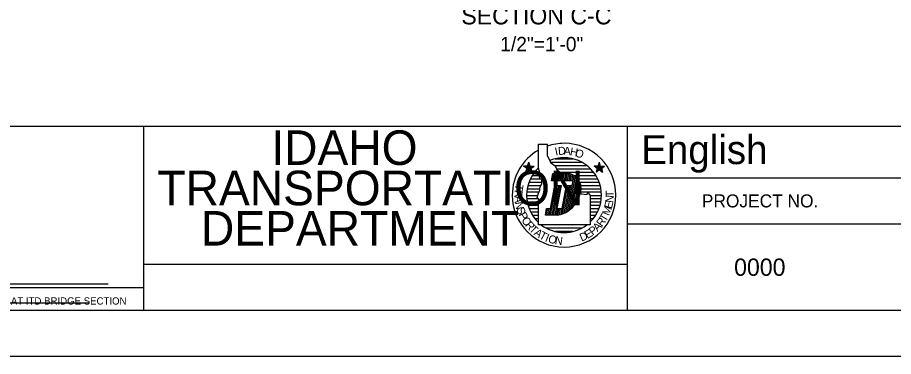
# Model space of a CAD drawing. Extents: x 0 to 68.6, y 0 to 47.1.
# Drawn here: x 25.26 to 44.28, y 0 to 7.35 of the extents above; entities that cross this region are included whole.
import ezdxf

# ---------------------------------------------------------------- set-up
doc = ezdxf.new("R2010")
doc.units = 0
for name, color, linetype in [('BORDER_ANNO_Cutsheet', 7, 'Continuous'), ('BRDG_ANNO_Anno-Large-Print', 7, 'Continuous'), ('BRDG_ANNO_Anno-Sheet', 7, 'Continuous'), ('BRDG_ANNO_Anno-Small-Print', 7, 'Continuous'), ('BRDG_ANNO_General-Notes', 7, 'Continuous')]:
    doc.layers.add(name, color=color, linetype=linetype)

msp = doc.modelspace()

# ---------------------------------------------------------------- linework, layer by layer
at = {"layer": 'BORDER_ANNO_Cutsheet'}
msp.add_lwpolyline([(0, 44), (68, 44), (68, 0), (0, 0)], close=True, dxfattribs=at)
at = {"layer": 'BRDG_ANNO_Anno-Large-Print'}
msp.add_line((23.799, 1.161), (26.811, 1.161), dxfattribs=at)
at = {"layer": 'BRDG_ANNO_Anno-Sheet'}
for p, q in [((3, 5), (38.5, 5)), ((28, 1), (28, 5)), ((38.5, 1), (38.5, 5)), ((38.5, 5), (67, 5)), ((36.569, 4.085), (36.569, 4.606)), ((36.569, 4.606), (36.766, 4.606)), ((36.766, 4.346), (36.766, 4.606)), ((36.331, 4.131), (36.359, 4.214)), ((36.359, 4.047), (36.359, 4.214)), ((36.386, 4.131), (36.359, 4.214)), ((36.766, 4.346), (36.819, 4.252)), ((36.819, 4.252), (36.829, 4.21)), ((36.829, 4.21), (36.932, 4.138)), ((36.834, 4.216), (37.501, 4.216)), ((36.93, 4.289), (37.316, 4.289)), ((37.864, 4.131), (37.891, 4.214)), ((37.891, 4.047), (37.891, 4.214)), ((37.919, 4.131), (37.891, 4.214)), ((36.402, 4.08), (36.245, 4.131)), ((36.331, 4.131), (36.245, 4.131)), ((36.315, 4.08), (36.245, 4.131)), ((36.386, 4.131), (36.288, 3.996)), ((36.315, 4.08), (36.288, 3.996)), ((36.359, 4.047), (36.288, 3.996)), ((36.315, 4.08), (36.474, 4.131)), ((36.331, 4.131), (36.43, 3.996)), ((36.359, 4.047), (36.43, 3.996)), ((36.386, 4.131), (36.474, 4.131)), ((36.402, 4.08), (36.474, 4.131)), ((36.402, 4.08), (36.43, 3.996)), ((36.484, 4.001), (36.587, 4.001)), ((36.549, 4.072), (36.572, 4.072)), ((36.589, 4.013), (36.569, 4.085)), ((36.589, 3.95), (36.589, 4.013)), ((36.93, 4.145), (37.614, 4.145)), ((36.932, 4.138), (36.965, 4.054)), ((36.957, 4.072), (37.701, 4.072)), ((36.965, 4.054), (37.069, 3.971)), ((37.031, 4.001), (37.765, 4.001)), ((37.935, 4.08), (37.776, 4.131)), ((37.847, 4.08), (37.776, 4.131)), ((37.864, 4.131), (37.776, 4.131)), ((37.919, 4.131), (37.82, 3.996)), ((37.847, 4.08), (37.82, 3.996)), ((37.891, 4.047), (37.82, 3.996)), ((37.847, 4.08), (38.005, 4.131)), ((37.864, 4.131), (37.962, 3.996)), ((37.891, 4.047), (37.962, 3.996)), ((37.919, 4.131), (38.005, 4.131)), ((37.935, 4.08), (38.005, 4.131)), ((37.935, 4.08), (37.962, 3.996)), ((36.394, 3.856), (36.596, 3.856)), ((36.434, 3.929), (36.585, 3.929)), ((36.589, 3.897), (36.589, 3.95)), ((36.6, 3.856), (36.589, 3.897)), ((36.641, 3.835), (36.6, 3.856)), ((36.641, 3.782), (36.641, 3.835)), ((36.85, 3.814), (36.881, 3.971)), ((37.322, 3.814), (36.85, 3.814)), ((36.879, 3.814), (36.907, 3.971)), ((36.881, 3.971), (37.225, 3.971)), ((36.91, 3.814), (36.94, 3.971)), ((36.942, 3.814), (36.971, 3.971)), ((36.974, 3.814), (37.004, 3.971)), ((37.005, 3.814), (37.035, 3.971)), ((37.038, 3.814), (37.066, 3.971)), ((37.069, 3.814), (37.099, 3.971)), ((37.101, 3.814), (37.13, 3.971)), ((37.133, 3.814), (37.163, 3.971)), ((37.165, 3.814), (37.194, 3.971)), ((37.196, 3.814), (37.226, 3.971)), ((37.199, 3.149), (37.344, 3.924)), ((37.227, 3.814), (37.256, 3.962)), ((37.235, 3.171), (37.373, 3.904)), ((37.26, 3.814), (37.286, 3.954)), ((37.273, 3.201), (37.399, 3.877)), ((37.291, 3.814), (37.315, 3.94)), ((37.304, 3.71), (37.322, 3.814)), ((37.311, 3.237), (37.425, 3.849)), ((37.337, 3.929), (37.815, 3.929)), ((37.351, 3.28), (37.45, 3.812)), ((37.42, 3.856), (37.855, 3.856)), ((38.5, 3.875), (44.5, 3.875)), ((36.325, 3.641), (36.596, 3.641)), ((36.341, 3.712), (36.623, 3.712)), ((36.362, 3.785), (36.637, 3.785)), ((36.6, 3.657), (36.62, 3.7)), ((36.6, 3.606), (36.6, 3.657)), ((36.62, 3.7), (36.641, 3.751)), ((36.641, 3.751), (36.641, 3.782)), ((36.829, 3.21), (36.922, 3.71)), ((36.832, 3.064), (36.954, 3.71)), ((36.865, 3.064), (36.986, 3.71)), ((36.896, 3.064), (37.017, 3.71)), ((36.922, 3.71), (37.06, 3.71)), ((36.929, 3.064), (37.05, 3.71)), ((37.06, 3.71), (36.966, 3.21)), ((37.087, 3.21), (37.181, 3.71)), ((37.094, 3.095), (37.209, 3.71)), ((37.127, 3.11), (37.24, 3.71)), ((37.163, 3.126), (37.273, 3.71)), ((37.181, 3.71), (37.304, 3.71)), ((37.394, 3.337), (37.474, 3.764)), ((37.444, 3.435), (37.491, 3.69)), ((37.465, 3.785), (37.886, 3.785)), ((37.489, 3.712), (37.909, 3.712)), ((37.495, 3.641), (37.925, 3.641)), ((36.312, 3.496), (36.555, 3.496)), ((36.315, 3.569), (36.581, 3.569)), ((36.316, 3.425), (36.562, 3.425)), ((36.538, 3.45), (36.557, 3.501)), ((36.569, 3.419), (36.538, 3.45)), ((36.557, 3.501), (36.569, 3.544)), ((36.569, 3.544), (36.6, 3.606)), ((37.481, 3.555), (37.496, 3.532)), ((37.485, 3.569), (37.935, 3.569)), ((37.496, 3.532), (37.559, 3.522)), ((37.559, 3.522), (37.621, 3.512)), ((37.621, 3.512), (37.652, 3.554)), ((37.652, 3.554), (37.694, 3.491)), ((37.69, 3.496), (37.938, 3.496)), ((37.694, 3.491), (37.694, 2.855)), ((37.695, 3.425), (37.934, 3.425)), ((36.326, 3.353), (36.596, 3.353)), ((36.343, 3.281), (36.567, 3.281)), ((36.589, 3.387), (36.569, 3.419)), ((36.569, 3.304), (36.6, 3.335)), ((36.569, 2.855), (36.569, 3.304)), ((36.6, 3.366), (36.589, 3.387)), ((36.6, 3.335), (36.6, 3.366)), ((37.694, 3.353), (37.924, 3.353)), ((37.694, 3.281), (37.907, 3.281)), ((36.367, 3.209), (36.565, 3.209)), ((36.399, 3.136), (36.565, 3.136)), ((36.44, 3.065), (36.566, 3.065)), ((36.719, 3.064), (36.746, 3.21)), ((36.985, 3.064), (36.719, 3.064)), ((36.737, 3.064), (36.765, 3.21)), ((36.746, 3.21), (36.829, 3.21)), ((36.77, 3.064), (36.797, 3.21)), ((36.801, 3.064), (36.829, 3.21)), ((36.96, 3.064), (36.987, 3.21)), ((36.966, 3.21), (37.087, 3.21)), ((36.992, 3.065), (37.02, 3.21)), ((37.026, 3.074), (37.051, 3.21)), ((37.06, 3.084), (37.082, 3.21)), ((37.694, 3.209), (37.883, 3.209)), ((37.694, 3.136), (37.85, 3.136)), ((37.694, 3.065), (37.81, 3.065)), ((36.491, 2.992), (36.565, 2.992)), ((36.555, 2.921), (36.567, 2.921)), ((37.694, 2.855), (36.569, 2.855)), ((37.694, 2.992), (37.76, 2.992)), ((38.5, 2.875), (44.5, 2.875)), ((37.501, 2.782), (36.744, 2.782)), ((37.317, 2.711), (36.935, 2.711)), ((28, 2), (38.5, 2))]:
    msp.add_line(p, q, dxfattribs=at)
msp.add_lwpolyline([(3, 43), (67, 43), (67, 1), (3, 1)], close=True, dxfattribs=at)
for centre, radius, start, end in [((37.125, 3.5), 1.125, 90, 108.596), ((37.125, 3.5), 1.125, 0, 90), ((37.125, 3.5), 1.125, 119.6331, 180), ((37.125, 3.5), 0.813, 90, 112.1452), ((37.125, 3.5), 0.813, 0, 90), ((37.125, 3.5), 0.813, 133.1926, 180), ((37.167, 3.648), 0.328, 343.4981, 79.7362), ((37.125, 3.5), 1.125, 180, 270), ((37.125, 3.5), 0.813, 180.2644, 226.7946), ((36.87, 3.676), 0.623, 280.6479, 348.7719), ((37.125, 3.5), 1.125, 270, 0), ((37.125, 3.5), 0.813, 314.427, 0), ((37.125, 3.5), 0.813, 232.5658, 270), ((37.125, 3.5), 0.813, 270, 307.4536)]:
    msp.add_arc(centre, radius, start, end, dxfattribs=at)
at = {"layer": 'BRDG_ANNO_Anno-Small-Print'}
for p, q in [((24.432, 1.573), (27.227, 1.573)), ((23, 1.5), (28, 1.5))]:
    msp.add_line(p, q, dxfattribs=at)

# ---------------------------------------------------------------- texts
at = {"layer": 'BRDG_ANNO_Anno-Sheet'}
for s, height, p in [('IDAHO', 0.75, (30.767, 4.156)), ('English', 0.625, (38.801, 4.174)), ('TRANSPORTATION', 0.75, (28.294, 3.281)), ('PROJECT NO.', 0.28125, (40.118, 3.235)), ('DEPARTMENT', 0.75, (29.239, 2.406)), ('0000', 0.375, (40.818, 1.75))]:
    msp.add_text(s, height=height, dxfattribs=at).set_placement(p)
for s, rotation, p in [('I', 11.9519, (36.944, 4.356)), ('D', 5.2118, (37.002, 4.369)), ('A', 357.8718, (37.114, 4.376)), ('H', 349.6318, (37.244, 4.367)), ('O', 342.1917, (37.349, 4.346)), ('T', 259.4265, (36.076, 3.751)), ('R', 266.0275, (36.053, 3.615)), ('A', 273.764, (36.046, 3.481)), ('N', 83.1932, (38.19, 3.326)), ('T', 90.4926, (38.204, 3.459)), ('N', 280.3758, (36.057, 3.342)), ('S', 287.9279, (36.086, 3.208)), ('M', 67.7139, (38.101, 3.041)), ('E', 75.6105, (38.159, 3.194)), ('P', 295.4976, (36.131, 3.081)), ('T', 59.0362, (38.027, 2.91)), ('O', 302.6446, (36.191, 2.96)), ('R', 309.9079, (36.267, 2.845)), ('T', 317.1211, (36.355, 2.742)), ('A', 45, (37.851, 2.701)), ('R', 52.3344, (37.947, 2.802)), ('A', 324.6375, (36.456, 2.651)), ('T', 331.7503, (36.569, 2.574)), ('D', 22.9887, (37.506, 2.491)), ('E', 30.5476, (37.631, 2.547)), ('P', 37.6656, (37.746, 2.619)), ('I', 337.0213, (36.699, 2.507)), ('O', 343.3287, (36.765, 2.481)), ('N', 351.6598, (36.917, 2.44))]:
    msp.add_text(s, height=0.174, rotation=rotation, dxfattribs=at).set_placement(p)
at = {"layer": 'BRDG_ANNO_Anno-Small-Print'}
msp.add_text('ORIGINAL STORED AT ITD BRIDGE SECTION', height=0.15643, dxfattribs=at).set_placement((23.125, 1.126))
at = {"layer": 'BRDG_ANNO_General-Notes'}
for s, height, p in [('SECTION C-C', 0.375, (34.894, 7.205)), ('1/2"=1\'-0"', 0.3125, (35.738, 6.622))]:
    msp.add_text(s, height=height, dxfattribs=at).set_placement(p)

doc.saveas('drawing.dxf')
